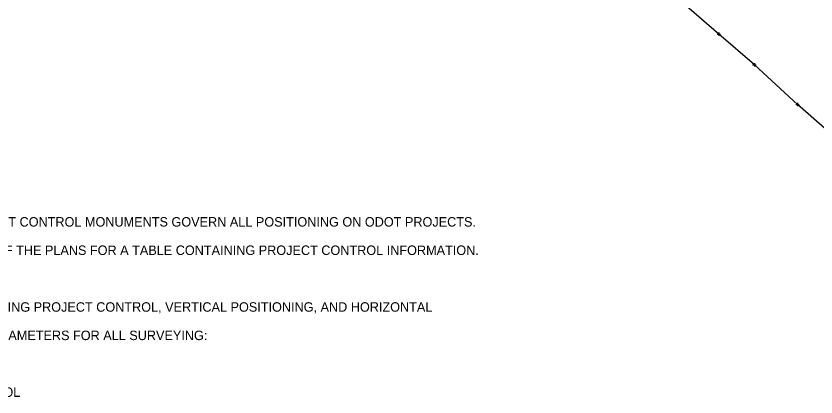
# Model space of a CAD drawing. Extents: x 2331247 to 2333939, y 279314 to 282014.
# Drawn here: x 2332112 to 2332348.6, y 280457.6 to 280570.3 of the extents above; entities that cross this region are included whole.
import ezdxf

# ---------------------------------------------------------------- set-up
doc = ezdxf.new("R2010")
doc.units = 0
for name, color, linetype in [('RD_X_GR_Lt', 7, 'Continuous'), ('Stream 1', 7, 'Continuous'), ('SV_X_Break_Lines', 7, 'Continuous'), ('SV_X_Text', 7, 'Continuous')]:
    doc.layers.add(name, color=color, linetype=linetype)

msp = doc.modelspace()

# ---------------------------------------------------------------- linework, layer by layer
at = {"layer": 'RD_X_GR_Lt'}
msp.add_open_spline([(2332445.29, 280499.77), (2332450.66, 280505.98), (2332463.27, 280522.36), (2332477.94, 280545.21), (2332486.44, 280568.86), (2332493.72, 280583.52), (2332494.06, 280601.38), (2332474.54, 280613.27), (2332449.57, 280625.63), (2332417.1, 280641.27), (2332387.74, 280657.01), (2332361.96, 280670.71), (2332336.96, 280685.78), (2332308.47, 280702.78), (2332280.69, 280721.1), (2332263.01, 280732.02), (2332256.02, 280736.68)], degree=3, dxfattribs=at)
at = {"layer": 'Stream 1'}
for p, q in [((2332319.43, 280564.95), (2332320.43, 280564.95)), ((2332319.93, 280565.45), (2332319.93, 280564.45)), ((2332319.93, 280564.95), (2332319.93, 280564.95)), ((2332330.4, 280556.39), (2332330.4, 280555.39)), ((2332329.9, 280555.89), (2332330.9, 280555.89)), ((2332330.4, 280555.89), (2332330.4, 280555.89)), ((2332343.16, 280544.64), (2332343.16, 280543.64)), ((2332342.66, 280544.14), (2332343.66, 280544.14)), ((2332343.16, 280544.14), (2332343.16, 280544.14))]:
    msp.add_line(p, q, dxfattribs=at)
at = {"layer": 'SV_X_Break_Lines'}
msp.add_lwpolyline([(2332424.57, 280473.01), (2332419.62, 280476.71), (2332415.82, 280479.78), (2332392.66, 280500.95), (2332367.94, 280522.49), (2332343.16, 280544.14), (2332330.4, 280555.89), (2332319.93, 280564.95), (2332292.85, 280588.47), (2332269.38, 280609.15), (2332258.93, 280616.47), (2332254.34, 280620.18), (2332227.49, 280638.02), (2332210.64, 280654.29), (2332193.94, 280674.12), (2332182.48, 280688.17), (2332174.82, 280693.64), (2332163.3, 280704.14)], dxfattribs=at)

# ---------------------------------------------------------------- texts
at = {"layer": 'SV_X_Text'}
for s, p in [('PRIMARY PROJECT CONTROL MONUMENTS GOVERN ALL POSITIONING ON ODOT PROJECTS.', (2332076.42, 280508.02)), ('SEE SHEET ___ OF THE PLANS FOR A TABLE CONTAINING PROJECT CONTROL INFORMATION.', (2332076.42, 280499.62)), ('USE THE FOLLOWING PROJECT CONTROL, VERTICAL POSITIONING, AND HORIZONTAL', (2332076.42, 280482.82)), ('POSITIONING PARAMETERS FOR ALL SURVEYING:', (2332076.42, 280474.42)), ('PROJECT CONTROL', (2332076.42, 280457.62))]:
    msp.add_text(s, height=2.8, dxfattribs=at).set_placement(p)

doc.saveas('drawing.dxf')
